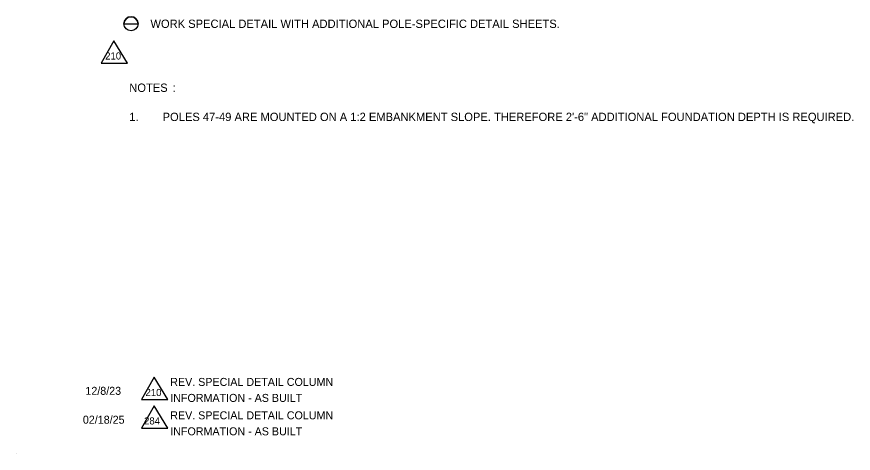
# Model space of a CAD drawing. Extents: x -816.7 to -800.7, y -2197.9 to -2187.9.
# Drawn here: x -816.67 to -809.64, y -2197.9 to -2194.23 of the extents above; entities that cross this region are included whole.
import ezdxf

# ---------------------------------------------------------------- set-up
doc = ezdxf.new("R2010")
doc.units = 0
for name, color, linetype in [('AdhocPoint_dp', 7, 'Continuous'), ('ScratchEle_dp', 7, 'Continuous'), ('TextLabel', 7, 'Continuous'), ('TextMinor', 7, 'Continuous')]:
    doc.layers.add(name, color=color, linetype=linetype)

msp = doc.modelspace()

# ---------------------------------------------------------------- linework, layer by layer
at = {"layer": 'AdhocPoint_dp'}
msp.add_line((-816.6686, -2197.8985), (-816.6686, -2197.8985), dxfattribs=at)
at = {"layer": 'ScratchEle_dp'}
for points in [[(-815.8525, -2194.4323), (-815.9603, -2194.6204), (-815.7396, -2194.6204)], [(-815.5137, -2197.2596), (-815.6215, -2197.4477), (-815.4008, -2197.4477)], [(-815.5137, -2197.4986), (-815.6215, -2197.6867), (-815.4008, -2197.6867)]]:
    msp.add_lwpolyline(points, close=True, dxfattribs=at)
at = {"layer": 'TextLabel'}
msp.add_line((-815.7681, -2194.2899), (-815.6496, -2194.2899), dxfattribs=at)
msp.add_line((-815.7681, -2194.2899), (-815.6496, -2194.2899), dxfattribs=at)
msp.add_circle((-815.7089, -2194.2899), 0.0593, dxfattribs=at)
msp.add_arc((-815.7089, -2194.2899), 0.0593, 0, 180, dxfattribs=at)

# ---------------------------------------------------------------- texts
at = {"layer": 'ScratchEle_dp'}
for s, p in [('210', (-815.9258, -2194.5903)), ('210', (-815.587, -2197.4175)), ('284', (-815.5991, -2197.6565))]:
    msp.add_text(s, height=0.05998, rotation=0, dxfattribs=at).set_placement(p)
at = {"layer": 'TextLabel'}
for s, p in [('WORK SPECIAL DETAIL WITH ADDITIONAL POLE-SPECIFIC DETAIL SHEETS.', (-815.5457, -2194.3249)), ('NOTES', (-815.7233, -2194.8621)), (':', (-815.3599, -2194.8621)), ('1.', (-815.7233, -2195.1071)), ('POLES 47-49 ARE MOUNTED ON A 1:2 EMBANKMENT SLOPE. THEREFORE 2\'-6" ADDITIONAL FOUNDATION DEPTH IS REQUIRED.', (-815.4433, -2195.1071))]:
    msp.add_text(s, height=0.07, dxfattribs=at).set_placement(p)
at = {"layer": 'TextMinor'}
for s, p in [('REV. SPECIAL DETAIL COLUMN ', (-815.3793, -2197.3326)), ('12/8/23', (-816.0919, -2197.4075)), ('INFORMATION - AS BUILT', (-815.3793, -2197.467)), ('REV. SPECIAL DETAIL COLUMN ', (-815.3793, -2197.6132)), ('02/18/25', (-816.1129, -2197.6501)), ('INFORMATION - AS BUILT', (-815.3793, -2197.7476))]:
    msp.add_text(s, height=0.0672, rotation=360, dxfattribs=at).set_placement(p)

doc.saveas('drawing.dxf')
